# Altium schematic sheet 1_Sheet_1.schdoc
size 304 x 215 mm; Name: A_A4; Symbol: A_A4; Device: A_A4; @Project Name: TK021F2699-RGB_转接板_椭圆-24位; REV: 1.0; Date: 2022-07-25; Sheet: 1/1; Draw By: zhouao; Company: NULL Studio; Convert to PCB: yes; Add into BOM: yes; Width: 1150; Height: 807; Region Start: 1; X Region Count: 1; Y Region Count: 1; Title Block Position: 3; @Page No: 1; @Page Count: 1; @Schematic Name: TK021F2699-RGB_转接板_24位_并联; @Board Name: TK021F2699-RGB_转接板_24位_并联; @Update Date: 2024-10-23; @Create Time: 19:04:46; @Update Time: 19:04:47; @Page Name: Sheet_1; @Create Date: 2024-10-23
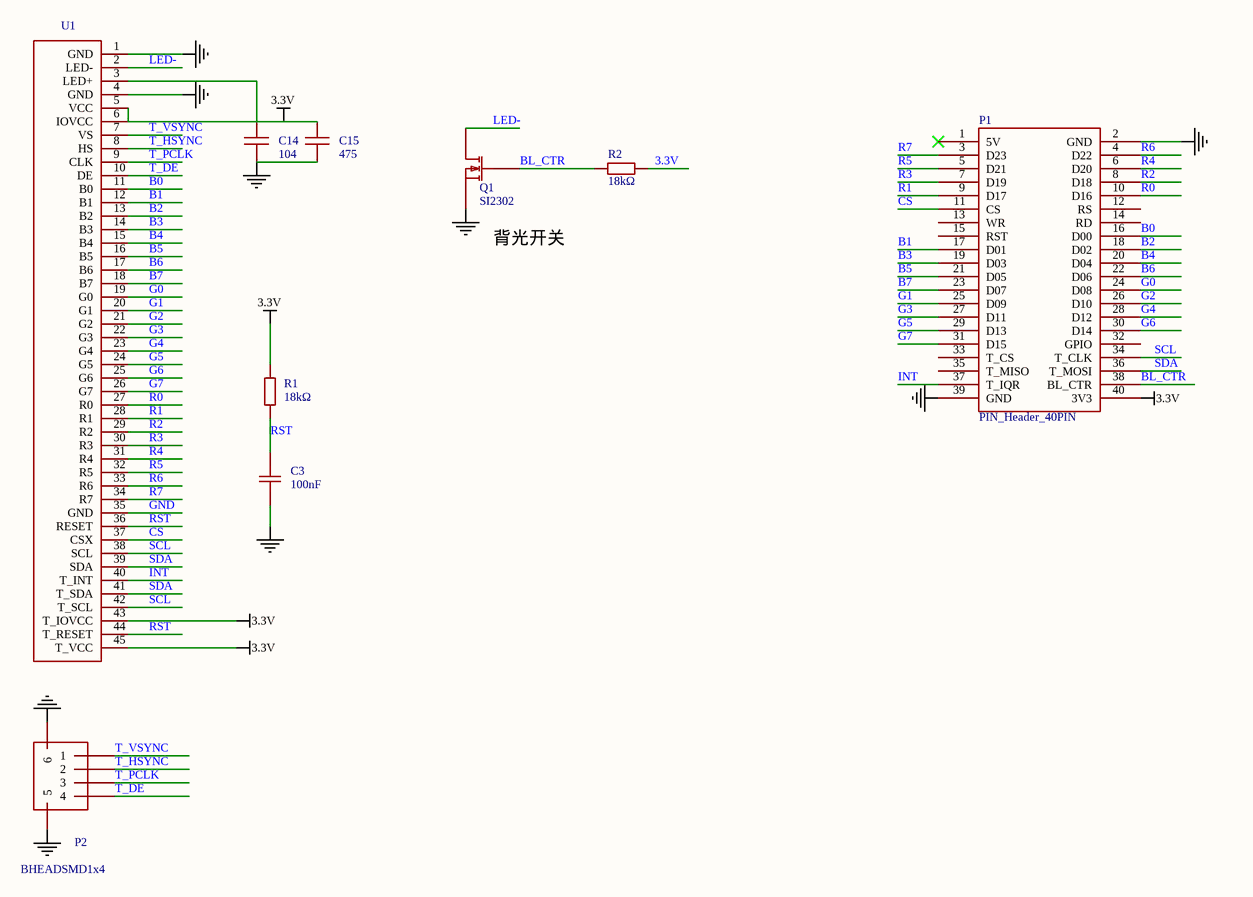
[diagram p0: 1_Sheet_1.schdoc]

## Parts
C3  100nF  [C0603]  (value not drawn)
C14  104  [C0603-1]  (value not drawn)
C15  475  [C0603-2]  (value not drawn)
P1  PIN_Header_40PIN  [P_Head_2x20]  (value not drawn)
P2  BHEADSMD1x4  [BHEADSMD1x4]  (value not drawn)
Q1  SI2302  [SOT23A]  (value not drawn)
R1  18kΩ  [R0603]  (value not drawn)
R2  18kΩ  [R0603]  (value not drawn)
U1  TK-RGB-45P  [TK043F-45P]  (value not drawn)

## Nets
3.3V: C14.1 C15.1 P1.40(3V3) R1.2 R2.2 U1.3(LED+) U1.5(VCC) U1.6(IOVCC) U1.43(T_IOVCC) U1.45(T_VCC)
GND: C3.2 C14.2 C15.2 P1.2(GND) P1.39(GND) P2.5 P2.6 Q1.2(S) U1.1(GND) U1.4(GND) U1.35(GND)
B0: P1.16(D00) U1.11(B0)
B1: P1.17(D01) U1.12(B1)
B2: P1.18(D02) U1.13(B2)
B3: P1.19(D03) U1.14(B3)
B4: P1.20(D04) U1.15(B4)
B5: P1.21(D05) U1.16(B5)
B6: P1.22(D06) U1.17(B6)
B7: P1.23(D07) U1.18(B7)
BL_CTR: P1.38(BL_CTR) Q1.1(G) R2.1
CS: P1.11(CS) U1.37(CSX)
G0: P1.24(D08) U1.19(G0)
G1: P1.25(D09) U1.20(G1)
G2: P1.26(D10) U1.21(G2)
G3: P1.27(D11) U1.22(G3)
G4: P1.28(D12) U1.23(G4)
G5: P1.29(D13) U1.24(G5)
G6: P1.30(D14) U1.25(G6)
G7: P1.31(D15) U1.26(G7)
INT: P1.37(T_IQR) U1.40(T_INT)
LED-: Q1.3(D) U1.2(LED-)
R0: P1.10(D16) U1.27(R0)
R1: P1.9(D17) U1.28(R1)
R2: P1.8(D18) U1.29(R2)
R3: P1.7(D19) U1.30(R3)
R4: P1.6(D20) U1.31(R4)
R5: P1.5(D21) U1.32(R5)
R6: P1.4(D22) U1.33(R6)
R7: P1.3(D23) U1.34(R7)
RST: C3.1 R1.1 U1.36(RESET) U1.44(T_RESET)
SCL: P1.34(T_CLK) U1.38(SCL) U1.42(T_SCL)
SDA: P1.36(T_MOSI) U1.39(SDA) U1.41(T_SDA)
T_DE: P2.4 U1.10(DE)
T_HSYNC: P2.2 U1.8(HS)
T_PCLK: P2.3 U1.9(CLK)
T_VSYNC: P2.1 U1.7(VS)

Not connected (* = marked no-connect by the designer): P1 1(5V)* 12(RS) 13(WR) 14(RD) 15(RST) 32(GPIO) 33(T_CS) 35(T_MISO)

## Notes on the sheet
- (near Q1) 背光开关

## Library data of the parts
C3 = CC0603KRX7R9BB104: 容值:100nF;精度:±10%;额定电压:50V;材质(温度系数):X7R;; Manufacturer: YAGEO(国巨); Symbol: CC0603KRX7R9BB104_1; Add into BOM: yes; Tolerance: ±10%; Voltage Rated: 50V; Temperature Coefficient: X7R
C14 = 104: Symbol: cap; Origin Footprint 2: C0402-2; Origin Footprint 3: C0402-3; Origin Footprint 5: C0603-2; Origin Footprint 6: C0603-3; Origin Footprint 7: C0805-1; Origin Footprint 8: C0805-2; Origin Footprint 9: C0805-3; Origin Footprint 10: Case B 3528; Add into BOM: yes; Reuse Block: 背光升压输入电源可以用3.3V---5V; Group ID: 1; Channel ID: $1e88
C15 = 475: Symbol: cap; Origin Footprint 2: C0402-1; Origin Footprint 3: C0402-2; Origin Footprint 4: C0402-3; Origin Footprint 5: C0603-1; Origin Footprint 6: C0603-3; Origin Footprint 7: C0805-1; Origin Footprint 8: C0805-2; Origin Footprint 9: C0805-3; Origin Footprint 10: Case B 3528; Add into BOM: yes; Reuse Block: 背光升压输入电源可以用3.3V---5V; Group ID: 1; Channel ID: $1e118
P1 = PIN_Header_40PIN: Add into BOM: yes
P2 = BHEADSMD1x4: Add into BOM: yes
Q1 = MOSFET-N: Add into BOM: yes
R1 R2 = 0603WAF1802T5E: 电阻类型:厚膜电阻;阻值:18kΩ;精度:±1%;功率:100mW;最大工作电压:75V;温度系数:±100ppm/℃;; Manufacturer: UNI-ROYAL(厚声); Symbol: 0603WAF1802T5E_1; Add into BOM: yes; Tolerance: ±1%; Power(Watts): 100mW; Overload Voltage (Max): 75V
U1 = TK-RGB-45P: Symbol: TK021F2699-24; Add into BOM: yes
